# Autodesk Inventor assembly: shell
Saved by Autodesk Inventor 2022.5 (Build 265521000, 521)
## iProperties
Created: 2024-12
Part Number: shell
Document SubType Name: Assembly
Designer: AdminForWorker
Title: shell
Author: AdminForWorker
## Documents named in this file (4)
- c:\worker\convert-fusion-r05-cosv3\tmp\job-1\35\temp\files\545dca92-a972-481a-9197-dd1a1176500e\shell.iam
- c:\worker\convert-fusion-r05-cosv3\tmp\job-1\35\temp\files\545dca92-a972-481a-9197-dd1a1176500e\outer.ipt
- c:\worker\convert-fusion-r05-cosv3\tmp\job-1\35\temp\files\545dca92-a972-481a-9197-dd1a1176500e\back_shell.ipt
- c:\worker\convert-fusion-r05-cosv3\tmp\job-1\35\temp\files\545dca92-a972-481a-9197-dd1a1176500e\mid_cover.ipt
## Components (3 placed, 3 different names)
1. outer:1
2. back_shell:1
3. mid_cover:1
